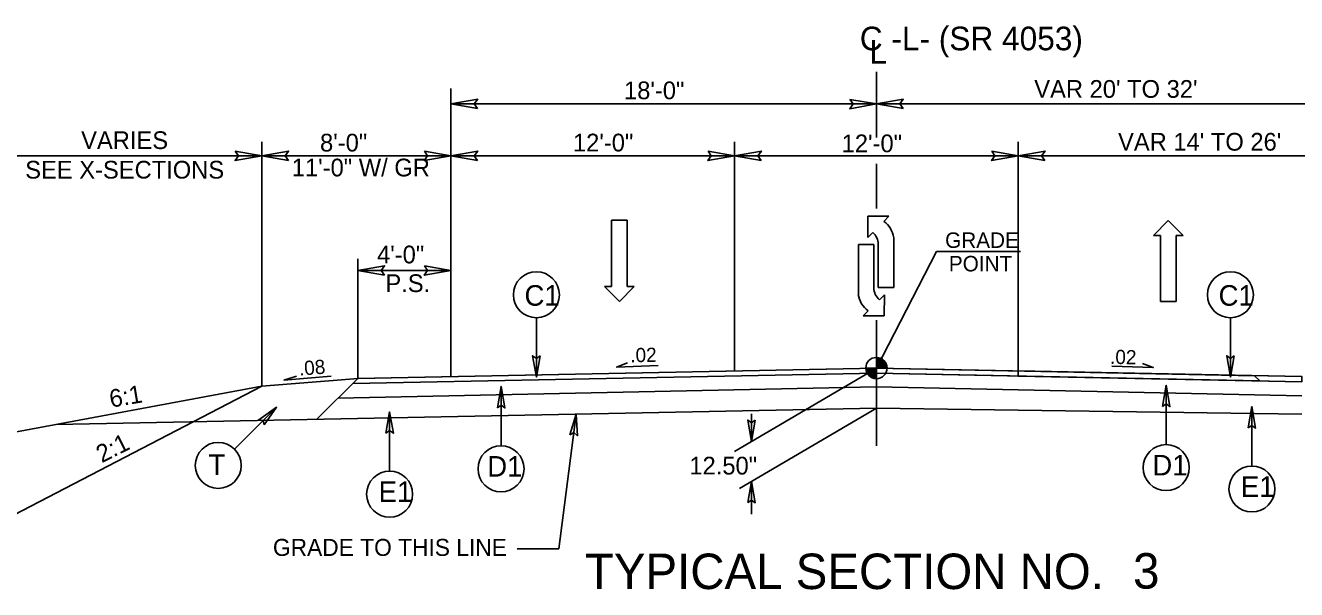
# Model space of a CAD drawing. Extents: x 981824 to 982276, y 44828 to 45204.
# Drawn here: x 982128.96 to 982171.98, y 45041.17 to 45060.27 of the extents above; entities that cross this region are included whole.
import ezdxf

# ---------------------------------------------------------------- set-up
doc = ezdxf.new("R2010")
doc.units = 0
for name, color, linetype in [('Default', 7, 'Continuous'), ('Old_Level_1', 7, 'Continuous'), ('Old_Level_11', 7, 'Continuous'), ('Old_Level_2', 7, 'Continuous'), ('Old_Level_20', 7, 'Continuous'), ('Old_Level_21', 7, 'Continuous'), ('Old_Level_3', 7, 'Continuous'), ('Prop Dimension Text', 7, 'Continuous'), ('Prop Lane Arrow CELL', 7, 'Continuous'), ('Prop Lane Arrow Through CELL', 7, 'Continuous'), ('Typical Terminator CELL', 7, 'Continuous')]:
    doc.layers.add(name, color=color, linetype=linetype)

msp = doc.modelspace()

# ---------------------------------------------------------------- linework, layer by layer
at = {"layer": 'Default'}
for points in [[(982150.369, 45048.753), (982148.969, 45048.704), (982149.335, 45048.843)], [(982165.728, 45048.731), (982167.128, 45048.683), (982166.762, 45048.821)]]:
    msp.add_lwpolyline(points, dxfattribs=at)
at = {"layer": 'Old_Level_1'}
for p, q in [((982157.761, 45058.693), (982157.761, 45056.475)), ((982143.361, 45058.128), (982143.361, 45048.379)), ((982143.361, 45057.607), (982157.761, 45057.607)), ((982157.761, 45057.607), (982175.348, 45057.607)), ((982136.961, 45056.322), (982136.961, 45048.056)), ((982152.961, 45056.322), (982152.961, 45048.571)), ((982162.561, 45056.322), (982162.561, 45048.571)), ((982127.423, 45055.854), (982136.961, 45055.854)), ((982136.961, 45055.854), (982143.361, 45055.854)), ((982143.361, 45055.854), (982152.961, 45055.854)), ((982152.961, 45055.854), (982157.761, 45055.854)), ((982157.761, 45055.854), (982162.561, 45055.854)), ((982162.561, 45055.854), (982175.348, 45055.854)), ((982157.761, 45055.581), (982157.761, 45054.067)), ((982140.212, 45052.362), (982140.212, 45048.316)), ((982157.761, 45048.667), (982159.791, 45052.609)), ((982140.212, 45051.971), (982143.361, 45051.971)), ((982157.761, 45050.285), (982157.761, 45046.041)), ((982157.761, 45048.667), (982157.761, 45049.027)), ((982157.761, 45048.495), (982140.037, 45048.141)), ((982157.761, 45048.667), (982140.222, 45048.317)), ((982157.761, 45048.667), (982152.955, 45045.846)), ((982157.401, 45048.667), (982157.761, 45048.667)), ((982157.758, 45048.494), (982172.158, 45048.208)), ((982157.76, 45048.307), (982157.761, 45048.667)), ((982157.761, 45048.667), (982157.76, 45048.307)), ((982157.761, 45048.667), (982172.161, 45048.379)), ((982158.121, 45048.667), (982157.761, 45048.667)), ((982127.423, 45043.098), (982136.961, 45048.056)), ((982127.423, 45046.278), (982136.961, 45048.056)), ((982136.961, 45048.056), (982140.222, 45048.317)), ((982137.71, 45048.255), (982139.307, 45048.397)), ((982137.71, 45048.255), (982138.132, 45048.397)), ((982140.212, 45048.316), (982138.824, 45046.935)), ((982157.762, 45048.032), (982139.538, 45047.646)), ((982157.762, 45048.032), (982172.162, 45047.729)), ((982157.761, 45047.315), (982130, 45046.758)), ((982157.761, 45047.315), (982153.129, 45044.596)), ((982157.761, 45047.315), (982172.161, 45047.113)), ((982147.016, 45042.555), (982147.603, 45047.111)), ((982153.534, 45047.125), (982153.534, 45046.185)), ((982153.534, 45044.834), (982153.534, 45043.721)), ((982145.597, 45042.555), (982147.016, 45042.555))]:
    msp.add_line(p, q, dxfattribs=at)
for points in [[(982157.764, 45049.027), (982157.764, 45049.027), (982157.764, 45048.667)], [(982157.771, 45049.027), (982157.771, 45048.667)], [(982157.779, 45049.026), (982157.779, 45048.667)], [(982157.786, 45049.026), (982157.786, 45048.667)], [(982157.793, 45049.025), (982157.793, 45048.667)], [(982157.8, 45049.025), (982157.8, 45048.667)], [(982157.807, 45049.024), (982157.807, 45048.667)], [(982157.815, 45049.023), (982157.815, 45048.667)], [(982157.822, 45049.022), (982157.822, 45048.667)], [(982157.829, 45049.021), (982157.829, 45048.667)], [(982157.836, 45049.019), (982157.836, 45048.667)], [(982157.843, 45049.017), (982157.843, 45048.667)], [(982157.851, 45049.016), (982157.851, 45048.667)], [(982157.858, 45049.013), (982157.858, 45048.667)], [(982157.865, 45049.012), (982157.865, 45048.667)], [(982157.872, 45049.009), (982157.872, 45048.667)], [(982157.879, 45049.007), (982157.879, 45048.667)], [(982157.887, 45049.005), (982157.887, 45048.667)], [(982157.894, 45049.001), (982157.894, 45048.667)], [(982157.901, 45048.998), (982157.901, 45048.667)], [(982157.908, 45048.995), (982157.908, 45048.667)], [(982157.915, 45048.992), (982157.915, 45048.667)], [(982157.923, 45048.989), (982157.923, 45048.667)], [(982157.93, 45048.985), (982157.93, 45048.667)], [(982157.937, 45048.981), (982157.937, 45048.667)], [(982157.944, 45048.977), (982157.944, 45048.667)], [(982157.951, 45048.973), (982157.951, 45048.667)], [(982157.959, 45048.968), (982157.959, 45048.667)], [(982157.966, 45048.963), (982157.966, 45048.667)], [(982157.973, 45048.957), (982157.973, 45048.667)], [(982157.98, 45048.953), (982157.98, 45048.667)], [(982157.987, 45048.947), (982157.987, 45048.667)], [(982157.995, 45048.941), (982157.995, 45048.667)], [(982158.002, 45048.934), (982158.002, 45048.667)], [(982158.009, 45048.928), (982158.009, 45048.667)], [(982158.016, 45048.921), (982158.016, 45048.667)], [(982158.023, 45048.913), (982158.023, 45048.667)], [(982158.031, 45048.905), (982158.031, 45048.667)], [(982158.038, 45048.897), (982158.038, 45048.667)], [(982158.045, 45048.888), (982158.045, 45048.667)], [(982157.403, 45048.667), (982157.403, 45048.628)], [(982157.41, 45048.667), (982157.41, 45048.585)], [(982157.417, 45048.667), (982157.417, 45048.56)], [(982157.424, 45048.667), (982157.424, 45048.538)], [(982157.431, 45048.667), (982157.431, 45048.521)], [(982157.439, 45048.667), (982157.439, 45048.506)], [(982157.446, 45048.667), (982157.446, 45048.493)], [(982157.453, 45048.667), (982157.453, 45048.48)], [(982157.46, 45048.667), (982157.46, 45048.469)], [(982157.467, 45048.667), (982157.467, 45048.458)], [(982157.475, 45048.667), (982157.475, 45048.449)], [(982157.482, 45048.667), (982157.482, 45048.44)], [(982157.489, 45048.667), (982157.489, 45048.431)], [(982157.496, 45048.667), (982157.496, 45048.423)], [(982157.503, 45048.667), (982157.503, 45048.415)], [(982157.511, 45048.667), (982157.511, 45048.408)], [(982157.518, 45048.667), (982157.518, 45048.401)], [(982157.525, 45048.667), (982157.525, 45048.395)], [(982157.532, 45048.667), (982157.532, 45048.389)], [(982157.539, 45048.667), (982157.539, 45048.383)], [(982157.547, 45048.667), (982157.547, 45048.377)], [(982157.554, 45048.667), (982157.554, 45048.373)], [(982157.561, 45048.667), (982157.561, 45048.368)], [(982157.568, 45048.667), (982157.568, 45048.363)], [(982157.575, 45048.667), (982157.575, 45048.358)], [(982157.583, 45048.667), (982157.583, 45048.354)], [(982157.59, 45048.667), (982157.59, 45048.35)], [(982157.597, 45048.667), (982157.597, 45048.346)], [(982157.604, 45048.667), (982157.604, 45048.343)], [(982157.611, 45048.667), (982157.611, 45048.34)], [(982157.619, 45048.667), (982157.619, 45048.337)], [(982157.626, 45048.667), (982157.626, 45048.333)], [(982157.633, 45048.667), (982157.633, 45048.33)], [(982157.64, 45048.667), (982157.64, 45048.328)], [(982157.647, 45048.667), (982157.647, 45048.325)], [(982157.655, 45048.667), (982157.655, 45048.323)], [(982157.662, 45048.667), (982157.662, 45048.321)], [(982157.669, 45048.667), (982157.669, 45048.319)], [(982157.676, 45048.667), (982157.676, 45048.317)], [(982157.683, 45048.667), (982157.683, 45048.316)], [(982157.691, 45048.667), (982157.691, 45048.314)], [(982157.698, 45048.667), (982157.698, 45048.313)], [(982157.705, 45048.667), (982157.705, 45048.312)], [(982157.712, 45048.667), (982157.712, 45048.31)], [(982157.719, 45048.667), (982157.719, 45048.309)], [(982157.727, 45048.667), (982157.727, 45048.309)], [(982157.734, 45048.667), (982157.734, 45048.308)], [(982157.741, 45048.667), (982157.741, 45048.308)], [(982157.748, 45048.667), (982157.748, 45048.307)], [(982157.755, 45048.667), (982157.755, 45048.307), (982157.755, 45048.307)], [(982158.052, 45048.878), (982158.052, 45048.667)], [(982158.059, 45048.868), (982158.059, 45048.667)], [(982158.067, 45048.857), (982158.067, 45048.667)], [(982158.074, 45048.845), (982158.074, 45048.667)], [(982158.081, 45048.832), (982158.081, 45048.667)], [(982158.088, 45048.817), (982158.088, 45048.667)], [(982158.095, 45048.8), (982158.095, 45048.667)], [(982158.103, 45048.78), (982158.103, 45048.667)], [(982158.11, 45048.755), (982158.11, 45048.667)], [(982158.117, 45048.718), (982158.117, 45048.667)]]:
    msp.add_lwpolyline(points, dxfattribs=at)
msp.add_circle((982157.76, 45048.667), 0.36, dxfattribs=at)
for start, end in [(359.9905, 89.9905), (179.9905, 269.9905)]:
    msp.add_arc((982157.76, 45048.667), 0.36, start, end, dxfattribs=at)
at = {"layer": 'Old_Level_11'}
for points in [[(982146.377, 45049.082), (982146.253, 45048.362), (982146.125, 45049.086), (982146.253, 45048.994)], [(982169.865, 45049.082), (982169.741, 45048.362), (982169.613, 45049.086), (982169.741, 45048.994)], [(982144.933, 45047.326), (982145.057, 45048.046), (982145.185, 45047.322), (982145.057, 45047.414)], [(982167.442, 45047.366), (982167.566, 45048.086), (982167.694, 45047.362), (982167.566, 45047.454)], [(982141.163, 45046.467), (982141.287, 45047.187), (982141.415, 45046.463), (982141.287, 45046.555)], [(982170.342, 45046.642), (982170.466, 45047.362), (982170.594, 45046.638), (982170.466, 45046.73)]]:
    msp.add_lwpolyline(points, close=True, dxfattribs=at)
at = {"layer": 'Old_Level_21'}
for points in [[(982157.761, 45048.495), (982140.037, 45048.141), (982140.212, 45048.316), (982157.761, 45048.667)], [(982157.761, 45048.667), (982170.559, 45048.411), (982170.735, 45048.236), (982157.758, 45048.494)], [(982162.561, 45048.571), (982172.161, 45048.379), (982172.158, 45048.208), (982162.558, 45048.398)]]:
    msp.add_lwpolyline(points, close=True, dxfattribs=at)
at = {"layer": 'Old_Level_3'}
msp.add_line((982159.791, 45052.609), (982162.636, 45052.609), dxfattribs=at)
at = {"layer": 'Prop Dimension Text'}
for p, q in [((982146.253, 45050.372), (982146.253, 45048.362)), ((982169.741, 45050.372), (982169.741, 45048.362)), ((982145.057, 45046.036), (982145.057, 45048.046)), ((982167.566, 45046.076), (982167.566, 45048.086)), ((982136.037, 45045.922), (982137.459, 45047.343)), ((982141.287, 45045.178), (982141.287, 45047.187)), ((982170.466, 45045.353), (982170.466, 45047.362))]:
    msp.add_line(p, q, dxfattribs=at)
for centre in [(982146.253, 45051.149), (982169.741, 45051.149), (982135.487, 45045.372), (982145.056, 45045.258), (982167.565, 45045.298), (982141.287, 45044.4), (982170.466, 45044.575)]:
    msp.add_circle(centre, 0.778, dxfattribs=at)
at = {"layer": 'Prop Lane Arrow CELL'}
for p, q in [((982158.181, 45053.807), (982157.469, 45053.807)), ((982157.469, 45053.807), (982157.469, 45053.087)), ((982158.013, 45053.631), (982158.181, 45053.807)), ((982157.469, 45053.087), (982157.637, 45053.255)), ((982157.149, 45052.847), (982157.149, 45051.159)), ((982157.677, 45052.847), (982157.149, 45052.847)), ((982157.677, 45051.383), (982157.677, 45052.847)), ((982157.821, 45052.855), (982157.821, 45051.391)), ((982158.349, 45051.391), (982158.349, 45053.079)), ((982157.821, 45051.391), (982158.349, 45051.391)), ((982158.029, 45051.151), (982157.861, 45050.983)), ((982158.021, 45050.431), (982158.029, 45051.151)), ((982157.485, 45050.607), (982157.317, 45050.439)), ((982157.317, 45050.439), (982158.021, 45050.431))]:
    msp.add_line(p, q, dxfattribs=at)
for centre, radius, start, end in [((982157.516, 45052.954), 0.84, 8.6761, 53.9878), ((982157.295, 45052.858), 0.524, 360, 49.6582), ((982157.977, 45051.285), 0.84, 188.6761, 233.9878), ((982158.198, 45051.381), 0.524, 180, 229.6582)]:
    msp.add_arc(centre, radius, start, end, dxfattribs=at)
at = {"layer": 'Prop Lane Arrow Through CELL'}
for p, q in [((982148.793, 45051.431), (982148.793, 45053.671)), ((982148.793, 45053.671), (982149.321, 45053.671)), ((982149.321, 45053.671), (982149.321, 45051.431)), ((982167.135, 45053.158), (982167.631, 45053.662)), ((982167.631, 45053.662), (982168.143, 45053.158)), ((982167.375, 45053.158), (982167.135, 45053.158)), ((982167.375, 45050.918), (982167.375, 45053.158)), ((982168.143, 45053.158), (982167.903, 45053.158)), ((982167.903, 45053.158), (982167.903, 45050.918)), ((982149.065, 45050.927), (982148.553, 45051.431)), ((982148.553, 45051.431), (982148.793, 45051.431)), ((982149.561, 45051.431), (982149.065, 45050.927)), ((982149.321, 45051.431), (982149.561, 45051.431)), ((982167.903, 45050.918), (982167.375, 45050.918))]:
    msp.add_line(p, q, dxfattribs=at)
at = {"layer": 'Typical Terminator CELL'}
for points in [[(982144.261, 45057.452), (982143.361, 45057.607), (982144.266, 45057.767), (982144.151, 45057.607)], [(982156.861, 45057.762), (982157.761, 45057.607), (982156.856, 45057.447), (982156.971, 45057.607)], [(982158.661, 45057.452), (982157.761, 45057.607), (982158.666, 45057.767), (982158.551, 45057.607)], [(982136.061, 45056.009), (982136.961, 45055.854), (982136.056, 45055.694), (982136.171, 45055.854)], [(982137.861, 45055.699), (982136.961, 45055.854), (982137.866, 45056.014), (982137.751, 45055.854)], [(982142.461, 45056.009), (982143.361, 45055.854), (982142.456, 45055.694), (982142.571, 45055.854)], [(982144.261, 45055.699), (982143.361, 45055.854), (982144.266, 45056.014), (982144.151, 45055.854)], [(982152.061, 45056.009), (982152.961, 45055.854), (982152.056, 45055.694), (982152.171, 45055.854)], [(982153.861, 45055.699), (982152.961, 45055.854), (982153.866, 45056.014), (982153.751, 45055.854)], [(982161.661, 45056.009), (982162.561, 45055.854), (982161.656, 45055.694), (982161.771, 45055.854)], [(982163.461, 45055.699), (982162.561, 45055.854), (982163.466, 45056.014), (982163.351, 45055.854)], [(982141.112, 45051.816), (982140.212, 45051.971), (982141.117, 45052.131), (982141.002, 45051.971)], [(982142.461, 45052.126), (982143.361, 45051.971), (982142.456, 45051.811), (982142.571, 45051.971)], [(982137.037, 45046.746), (982137.459, 45047.343), (982136.856, 45046.921), (982137.012, 45046.896)], [(982147.39, 45046.412), (982147.603, 45047.111), (982147.64, 45046.377), (982147.524, 45046.484)], [(982153.658, 45046.905), (982153.534, 45046.185), (982153.406, 45046.909), (982153.534, 45046.817)], [(982153.41, 45044.114), (982153.534, 45044.834), (982153.662, 45044.11), (982153.534, 45044.202)]]:
    msp.add_lwpolyline(points, close=True, dxfattribs=at)

# ---------------------------------------------------------------- texts
at = {"layer": 'Old_Level_1'}
for s, height, p in [('C -L- (SR 4053)', 0.8, (982157.197, 45059.424)), ('L', 0.8, (982157.528, 45058.974)), ('18\'-0"', 0.6, (982149.218, 45057.768)), ("VAR 20' TO 32'", 0.6, (982163.102, 45057.816)), ('VARIES', 0.6, (982130.847, 45056.082)), ("VAR 14' TO 26'", 0.6, (982165.937, 45056.028)), ('8\'-0"', 0.6, (982138.931, 45055.999)), ('12\'-0"', 0.6, (982147.49, 45056.001)), ('12\'-0"', 0.6, (982156.584, 45055.974)), ('11\'-0" W/ GR', 0.6, (982137.975, 45055.156)), ('SEE X-SECTIONS', 0.6, (982128.954, 45055.082)), ('4\'-0"', 0.6, (982140.86, 45052.212)), ('P.S.', 0.6, (982141.143, 45051.241)), ('12.50"', 0.6, (982151.43, 45045.066))]:
    msp.add_text(s, height=height, dxfattribs=at).set_placement(p)
for s, rotation, p in [('6:1', 9.4617, (982131.854, 45047.327)), ('2:1', 26.5646, (982131.545, 45045.444))]:
    msp.add_text(s, height=0.6, rotation=rotation, dxfattribs=at).set_placement(p)
at = {"layer": 'Old_Level_2'}
for s, rotation, p in [('.02  ', 1.144, (982149.435, 45048.863)), ('.08', 4.5739, (982138.236, 45048.411)), ('.02  ', 358.856, (982165.663, 45048.812))]:
    msp.add_text(s, height=0.48, rotation=rotation, dxfattribs=at).set_placement(p)
at = {"layer": 'Old_Level_20'}
for s, p in [('C1', (982145.851, 45050.779)), ('C1', (982169.34, 45050.779)), ('T ', (982135.158, 45045.054)), ('D1', (982144.59, 45044.994)), ('D1', (982167.099, 45045.034)), ('E1', (982140.914, 45044.135)), ('E1', (982170.094, 45044.31))]:
    msp.add_text(s, height=0.696, dxfattribs=at).set_placement(p)
at = {"layer": 'Old_Level_3'}
for s, height, p in [('GRADE TO THIS LINE', 0.576, (982137.337, 45042.31)), ('TYPICAL SECTION NO.  ', 1.2, (982147.894, 45041.188)), ('3 ', 1.2, (982166.446, 45041.204))]:
    msp.add_text(s, height=height, dxfattribs=at).set_placement(p)
at = {"layer": 'Prop Dimension Text'}
for s, p in [('GRADE', (982160.084, 45052.735)), ('POINT', (982160.211, 45051.94))]:
    msp.add_text(s, height=0.5248, dxfattribs=at).set_placement(p)

doc.saveas('drawing.dxf')
